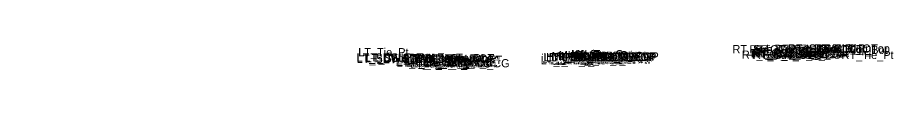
# Model space of a CAD drawing. Extents: x -26 to 4229, y -10 to 9523.
# Drawn here: x 2000 to 2215, y 8999.6 to 9006 of the extents above; entities that cross this region are included whole.
import ezdxf

# ---------------------------------------------------------------- set-up
doc = ezdxf.new("R2010")
doc.units = 0
doc.layers.add('Default', color=7, linetype='Continuous')

msp = doc.modelspace()

# ---------------------------------------------------------------- texts
at = {"layer": 'Default'}
for s, height, p in [('RT_SDWK_Out_Top', 2, (2189.19, 9003.88)), ('RT_Shld_O', 2, (2195.54, 9003.86)), ('CSLP_Pnt', 2, (2197.87, 9003.9)), ('LT_Tie_Pt', 2, (2083.65, 9002.96)), ('LT_PV1_OEEOP', 2, (2129.12, 9001.74)), ('LT_PV1_IEEOP', 2, (2129.77, 9001.74)), ('LT_PV1_PGL', 2, (2131.03, 9001.86)), ('MI_Face In', 2, (2131.15, 9002.03)), ('MI_Bot In', 2, (2132.13, 9001.86)), ('MI_Top In', 2, (2132.86, 9002.28)), ('RT_PV2_OEEOP', 2, (2135.74, 9001.8)), ('MI_Crown', 2, (2135.94, 9002.52)), ('RT_PV1_OEEOP', 2, (2136.31, 9001.92)), ('RT_PV2_IEEOP', 2, (2136.39, 9001.8)), ('MI_Face Out', 2, (2136.74, 9002.22)), ('MI_Top Out', 2, (2136.95, 9002.47)), ('RT_PV1_IEEOP', 2, (2136.96, 9001.92)), ('RT_PV2_PGL1', 2, (2137.32, 9001.8)), ('RT_PV2_PGL', 2, (2137.65, 9001.8)), ('MI_Bot Out', 2, (2137.74, 9002.05)), ('RT_PV1_PGL', 2, (2138.22, 9002.05)), ('RT_Sub_Trench_Out_DLT', 2, (2175.52, 9003.71)), ('RT_Sub_OEOT_CG', 2, (2177.82, 9002.36)), ('RT_CG_Top_Face', 2, (2179.71, 9003.66)), ('RT_CG1_Shelf_Out', 2, (2180, 9002.69)), ('RT_CG_Bot_IE', 2, (2180.37, 9002.61)), ('RT_Sub_OEOT', 2, (2180.53, 9002.32)), ('RT_PV2_OEOT', 2, (2180.63, 9002.94)), ('RT_PV3_OEOT', 2, (2180.63, 9002.69)), ('RT_CG_Top_Gut', 2, (2180.69, 9003.16)), ('RT_PV1_OEOT', 2, (2181.19, 9003.19)), ('RT_CG_Top_BOC', 2, (2181.24, 9003.66)), ('RT_CG_Bot_BOC', 2, (2181.27, 9002.67)), ('RT_Sub_OEOP', 2, (2183.81, 9002.44)), ('RT_SDWK_In_Top', 2, (2185.81, 9003.78)), ('RT_SDWK_In_Bot', 2, (2185.84, 9003.44)), ('RT_SDWK_Out_Bot', 2, (2189.22, 9003.54)), ('RT_Tie_Pt', 2, (2202.28, 9002.28)), ('LT_SDWK_Out_Top', 2, (2083.24, 9001.67)), ('LT_SDWK_Out_Bot', 2, (2083.27, 9001.33)), ('LT_CSLP_Pnt', 2, (2085.17, 9001.69)), ('LT_Sub_Trench_Out_DLT', 2, (2085.48, 9001.5)), ('LT_SDWK_In_Top', 2, (2089.86, 9001.57)), ('LT_SDWK_In_Bot', 2, (2089.89, 9001.23)), ('LT_CG1_Shelf_Out', 2, (2093.05, 9000.43)), ('LT_CG_Top_Face', 2, (2094.76, 9001.45)), ('LT_CG_Top_BOC', 2, (2095.28, 9001.45)), ('LT_CG_Bot_BOC', 2, (2095.31, 9000.44)), ('LT_CG_Top_Gut', 2, (2095.74, 9000.95)), ('LT_Sub_OEOP', 2, (2096.35, 9000.17)), ('LT_Sub_OEOT_CG', 2, (2096.87, 9000.25)), ('LT_CG_Bot_IE', 2, (2099.41, 9000.5)), ('LT_Sub_OEOT', 2, (2099.58, 9000.21)), ('LT_PV2_OEOT', 2, (2099.67, 9000.84)), ('LT_PV3_OEOT', 2, (2099.67, 9000.59)), ('LT_PV1_OEOT', 2, (2100.24, 9001.09)), ('LT_Sub_OEEOP', 2, (2128.46, 9000.99)), ('LT_PV2_OEEOP', 2, (2128.56, 9001.61)), ('LT_PV3_OEEOP', 2, (2128.56, 9001.36)), ('LT_PV2_IEEOP', 2, (2129.2, 9001.61)), ('LT_PV2_PGL1', 2, (2130.13, 9001.61)), ('LT_PV3_PGL1', 2, (2130.13, 9001.36)), ('LT_PV2_PGL', 2, (2130.46, 9001.61)), ('LT_PV4_PGL', 2, (2130.46, 9000.99)), ('RT_Sub_OEEOP', 2, (2135.65, 9001.17)), ('RT_PV3_OEEOP', 2, (2135.74, 9001.55)), ('RT_PV3_PGL1', 2, (2137.32, 9001.55)), ('RT_PV4_PGL', 2, (2137.65, 9001.17)), ('-', 0.0001, (2000, 9000)), ('-', 0.0001, (2000, 9000)), ('-', 0.0001, (2000, 9000)), ('-', 0.0001, (2000, 9000)), ('-', 0.0001, (2000, 9000)), ('-', 0.0001, (2000, 9000)), ('-', 0.0001, (2000, 9000))]:
    msp.add_text(s, height=height, dxfattribs=at).set_placement(p)

doc.saveas('drawing.dxf')
